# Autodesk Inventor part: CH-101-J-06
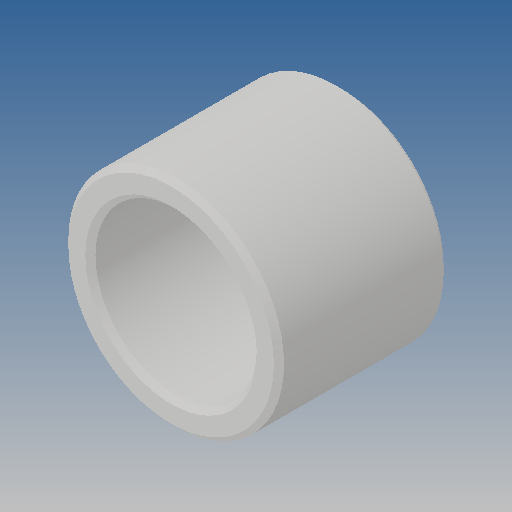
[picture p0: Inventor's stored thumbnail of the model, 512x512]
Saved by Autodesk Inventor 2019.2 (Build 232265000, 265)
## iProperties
Created: 2012-09
Part Number: CH-101-J-06
Material: Ogólny
Document SubType Name: Modeling
Designer: CADENGINEERING4
Density: 1 g/cm^3
Appearance: Domyślna
Author: CADENGINEERING4
Revision Number: ÈÎºÎ
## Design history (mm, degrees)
feature "µ¹½Ç1"
node "Bryła1"
